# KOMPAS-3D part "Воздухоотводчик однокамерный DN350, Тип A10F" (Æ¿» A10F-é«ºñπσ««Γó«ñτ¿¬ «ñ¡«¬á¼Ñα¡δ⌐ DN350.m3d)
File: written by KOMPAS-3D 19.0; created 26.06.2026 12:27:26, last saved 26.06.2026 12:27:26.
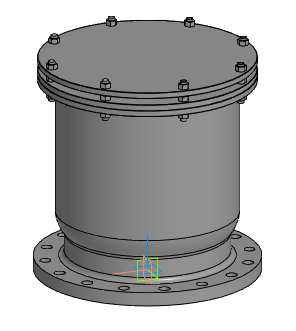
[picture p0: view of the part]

Document properties: Автор: Энергия; Полное имя файла: Z:\3.Личные\kachalov\001_3d для проектировщиков\х.х Тип A10F Воздухоотводчик однокамерный фланцевый\_step\Тип A10F-Воздухоотводчик однокамерный DN350.m3d

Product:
- Part/product: Воздухоотводчик однокамерный DN350  | designation Тип A10F

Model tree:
1. Операция без истории:1  (labels: Тип A10F; Воздухоотводчик однокамерный DN350)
